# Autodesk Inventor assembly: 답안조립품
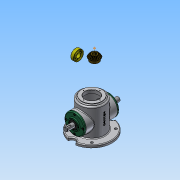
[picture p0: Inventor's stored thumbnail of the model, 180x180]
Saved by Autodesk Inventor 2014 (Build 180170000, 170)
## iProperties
Created: 2018-04
Part Number: 답안조립품
Document SubType Name: Assembly
Designer: NET
Author: NET
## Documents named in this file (13)
- C:\Users\NET\Desktop\480407V1027\답안조립품.iam
- C:\Users\NET\Desktop\480407V1027\본체.ipt
- C:\Users\NET\Desktop\480407V1027\메인 축.ipt
- 메인 축.ipt
- C:\Users\NET\Desktop\480407V1027\메인 베벨기어.ipt
- C:\Users\NET\Desktop\480407V1027\키 5x5.ipt
- C:\Users\NET\Desktop\480407V1027\베어링 6203.ipt
- C:\Users\NET\Desktop\480407V1027\오일 실.ipt
- 오일 실.ipt
- C:\Users\NET\Desktop\480407V1027\커버.ipt
- C:\Users\NET\Desktop\480407V1027\볼트 M4.ipt
- 볼트 M4.ipt
- C:\Users\NET\Desktop\480407V1027\서브 베벨기어.ipt
